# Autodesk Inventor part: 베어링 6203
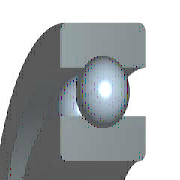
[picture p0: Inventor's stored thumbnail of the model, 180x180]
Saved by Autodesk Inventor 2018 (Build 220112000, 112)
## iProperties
IsCustomPart: 0
Created: 2016-05
Part Number: 베어링 6203
Material: 강, 연강
Description: 깊은 그루브 볼 베어링
Document SubType Name: Modeling
Standard: KS B 2023
Designer: mduedu
Standards Organization: KS
Language: ko-KR
Size Designation: 6203 - 17 x 40 x 12
Categories: <MemberInstance><Categories><Category DisplayName="샤프트 부품" InternalName="7f7aeb1f-a693-4053-b835-cee3144e0d98" Mnemonic="SHFT"><Category DisplayName="베어링" Inter
Density: 1 g/cm^3
Appearance: 노란색
Author: mduedu
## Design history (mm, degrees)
sketch "스케치" dims "d0" = 5.98 (= -0.26 x WD + 0.26 x BD)
  geometry: L1 (3.01, 14.25)-(8.99, 14.25); L2 (6, 14.25)-(6, 11.26); L3 (6, 14.25)-(6, 17.24); L4 (3.778, 12.249)-(0, 12.249); L5 (0, 8.5)-(12, 8.5); L6 (3.778, 16.251)-(0, 16.251); L7 (0, 20)-(12, 20); L8 (12, 8.5)-(12, 12.249); L9 (8.222, 12.249)-(12, 12.249); L10 (8.222, 16.251)-(12, 16.251); L11 (12, 20)-(12, 16.251); L12 (-1.4, 0)-(8.4, 0) reference; L13 (0, -0.3)-(0, 5.3) reference
  constraints: 22 end point, 4 point on line, 2 collinear, 2 perpendicular, 2 symmetric about line, 1 midpoint, 1 parallel, 14 other
  dimensions: "d9" = 17 diameter of L5 L12 (= WD); "d11" = 40 diameter of L7 L12 (= BD); "d12" = 12 distance between parallel lines of L8 L13 (= KB); "d13" = 24.498 diameter of L9 L12 (= 0.326 x BD + 0.674 x WD)
revolve "본체" stored, may be unused: angle "d6" = 90 deg
revolve "볼" stored, may be unused: angle "d7" = 90 deg
pattern_circular "IDS_ARRAYBALL[SIMPL:T]" dims angle "d3" = 360 deg
body "Solid1"
fillet "모깎기1" dims "d1" = 0.6 (= KRS)
other parameters: "WD" = 17 [user parameter; used in 5 equation terms], "BD" = 40 [user parameter; used in 5 equation terms], "KB" = 12 [user parameter; used in 1 equation term], "KRS" = 0.6 [user parameter; used in 1 equation term], "d4" = 0, "d5" = 0, "d8" = 0, "d14" = 0, "d15" = 0, "BBA" = 0 [user parameter], "BC0" = 4750000 [user parameter], "BC" = 9560000 [user parameter], "WR" = 8.5 (= 0.5 x WD) [user parameter]
